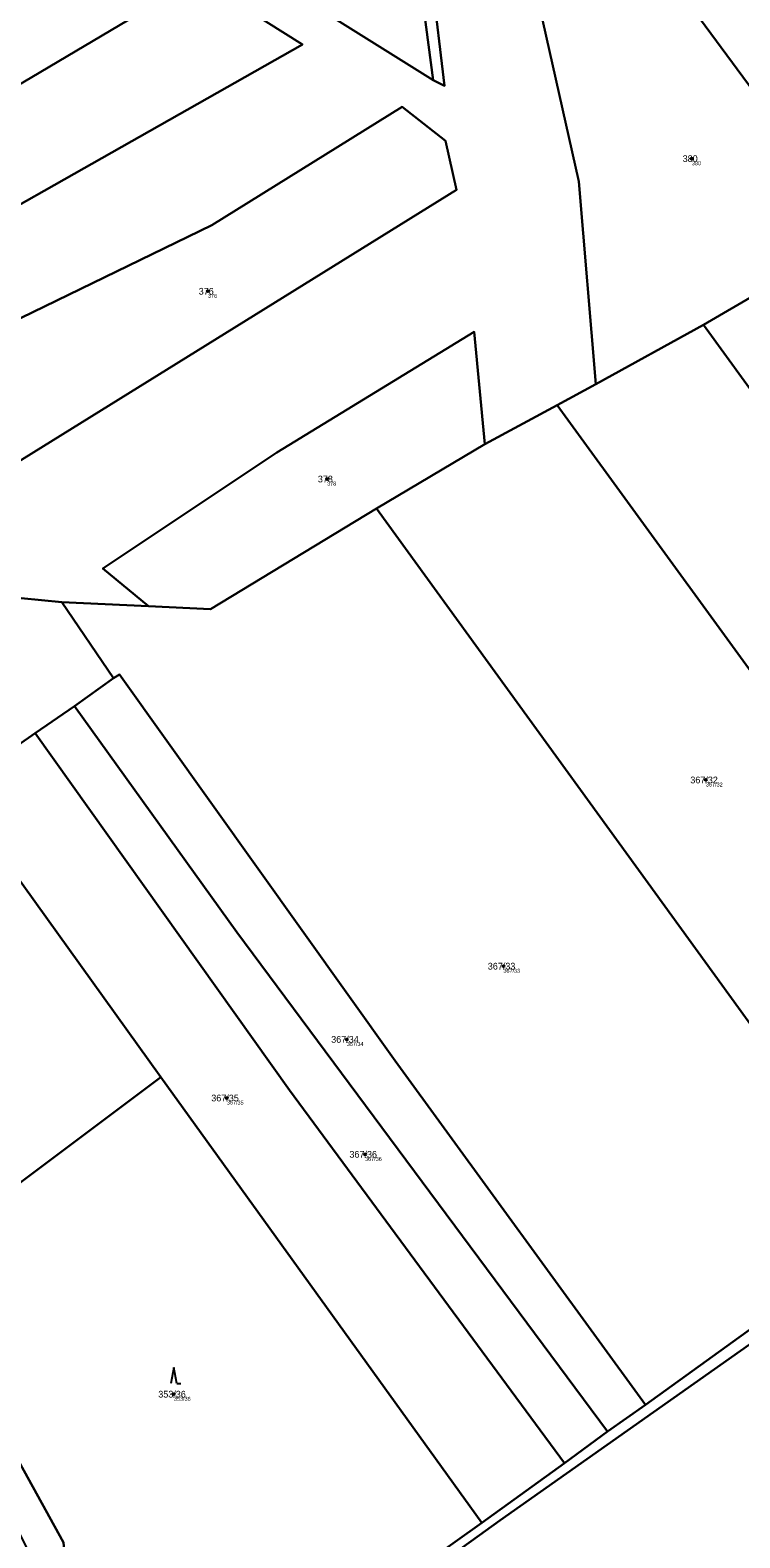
# Model space of a CAD drawing. Extents: x -700238 to -698499, y -1070626 to -1068006.
# Drawn here: x -699862.2 to -699683.1, y -1070432.3 to -1070051.8 of the extents above; entities that cross this region are included whole.
import ezdxf

# ---------------------------------------------------------------- set-up
doc = ezdxf.new("R2010")
doc.units = 0
for name, color, linetype in [('Definiční body', 7, 'Continuous'), ('Hranice parcel', 7, 'Continuous'), ('Parcelní čísla', 7, 'Continuous'), ('Polygon parcely', 7, 'Continuous'), ('Značky kultur', 7, 'Continuous')]:
    doc.layers.add(name, color=color, linetype=linetype)

msp = doc.modelspace()

# ---------------------------------------------------------------- linework, layer by layer
at = {"layer": 'Definiční body'}
for centre in [(-699695.22, -1070084.23994), (-699817.36, -1070117.69994), (-699787.29, -1070165.07994), (-699691.67, -1070241.01994), (-699742.78, -1070288.01994), (-699782.3, -1070306.48994), (-699812.57, -1070321.28994), (-699777.7, -1070335.49994), (-699825.94, -1070396.02994)]:
    msp.add_circle(centre, 0.25, dxfattribs=at)
at = {"layer": 'Hranice parcel'}
for p, q in [((-699760.48, -1070064.46), (-699764.05, -1070037.6)), ((-699692.3, -1070126.13), (-699719.44, -1070141.14)), ((-699719.44, -1070141.14), (-699729.26, -1070146.47)), ((-699729.26, -1070146.47), (-699747.49, -1070156.31)), ((-699747.49, -1070156.31), (-699774.82, -1070172.56)), ((-699841.16, -1070215.36), (-699854.27, -1070196.19)), ((-699832.38, -1070197.19), (-699854.27, -1070196.19)), ((-699851.06, -1070222.38), (-699841.16, -1070215.36)), ((-699860.99, -1070229.24), (-699851.06, -1070222.38)), ((-699881.39, -1070243.41), (-699860.99, -1070229.24)), ((-699881.39, -1070243.41), (-699829.22, -1070316.05)), ((-699829.22, -1070316.05), (-699882.86, -1070356.11)), ((-699748.23, -1070428.52), (-699829.22, -1070316.05)), ((-699643.87, -1070353.19), (-699706.96, -1070398.68)), ((-699706.96, -1070398.68), (-699716.55, -1070405.48)), ((-699716.55, -1070405.48), (-699727.35, -1070413.42)), ((-699727.35, -1070413.42), (-699748.23, -1070428.52)), ((-699823.69, -1070482.27), (-699748.23, -1070428.52))]:
    msp.add_line(p, q, dxfattribs=at)
for points in [[(-699773.88, -1069925.87), (-699775.47, -1069950.06), (-699776.09, -1069961.97), (-699774.25, -1069975.35), (-699760.75, -1070039.69), (-699757.63, -1070065.88), (-699760.48, -1070064.46)], [(-699760.48, -1070064.46), (-699814.07, -1070030.89), (-699916.79, -1069973.61), (-699963.55, -1069943.05)], [(-699854.27, -1070196.19), (-699869.64, -1070194.62), (-699892.83, -1070188.84), (-699913.08, -1070162.82), (-699928.47, -1070131.78), (-699793.52, -1070055.46), (-699819.94, -1070038.73), (-699903.8, -1070088.48), (-699881.47, -1070036.48), (-699859.27, -1070018.12), (-699893.51, -1069998.97), (-699909.95, -1070034.69), (-699926.64, -1070077.05), (-699936.46, -1070111.92), (-699945.42, -1070093.75), (-699957.78, -1070077.02), (-699945.33, -1070038.99), (-699924.07, -1069992.37), (-699973.03, -1069961.64)], [(-699719.44, -1070141.14), (-699723.72, -1070090.01), (-699733.66, -1070045.81), (-699736.31, -1069990.62)], [(-699736.31, -1069990.62), (-699727.1, -1070003.14), (-699698.54, -1070041.6), (-699662.16, -1070090.9)], [(-699882.78, -1070133.22), (-699816.4, -1070100.98), (-699768.36, -1070071.18), (-699757.42, -1070079.73), (-699754.62, -1070092.08), (-699868.61, -1070162.84), (-699882.78, -1070133.22)], [(-699667.65, -1070125.9), (-699678.56, -1070118.21), (-699692.3, -1070126.13)], [(-699832.38, -1070197.19), (-699843.91, -1070187.63), (-699799.97, -1070158.41), (-699750.15, -1070127.96), (-699747.49, -1070156.31)], [(-699692.3, -1070126.13), (-699631.14, -1070210.34), (-699566.95, -1070298.71)], [(-699729.26, -1070146.47), (-699663.22, -1070237.21), (-699601.03, -1070322.49)], [(-699774.82, -1070172.56), (-699816.69, -1070197.91), (-699832.38, -1070197.19)], [(-699774.82, -1070172.56), (-699708.7, -1070263.67), (-699643.87, -1070353.19)], [(-699841.16, -1070215.36), (-699839.71, -1070214.44), (-699770.11, -1070311.9), (-699706.96, -1070398.68)], [(-699851.06, -1070222.38), (-699810.03, -1070279.46), (-699716.55, -1070405.48)], [(-699727.35, -1070413.42), (-699796.81, -1070319.27), (-699860.99, -1070229.24)], [(-699882.86, -1070356.11), (-699869.32, -1070405.39), (-699853.83, -1070433.45), (-699852.48, -1070448.98)], [(-699822, -1070484.36), (-699743.66, -1070427.93), (-699677.85, -1070381.45)]]:
    msp.add_lwpolyline(points, dxfattribs=at)
at = {"layer": 'Polygon parcely'}
for points in [[(-699764.05, -1070037.6), (-699857.82, -1069980.05), (-699953.34, -1069921.42), (-699963.55, -1069943.05), (-699916.79, -1069973.61), (-699814.07, -1070030.89), (-699760.48, -1070064.46)], [(-699776.82, -1069919.37), (-699778.54, -1069940.11), (-699779.64, -1069961.35), (-699777.09, -1069979.45), (-699771.94, -1070003.65), (-699764.05, -1070037.6), (-699760.48, -1070064.46), (-699757.63, -1070065.88), (-699760.75, -1070039.69), (-699774.25, -1069975.35), (-699776.09, -1069961.97), (-699775.47, -1069950.06), (-699773.88, -1069925.87)], [(-699660.76, -1070101.89), (-699662.16, -1070090.9), (-699698.54, -1070041.6), (-699727.1, -1070003.14), (-699736.31, -1069990.62), (-699733.66, -1070045.81), (-699723.72, -1070090.01), (-699719.44, -1070141.14), (-699692.3, -1070126.13), (-699678.56, -1070118.21), (-699667.65, -1070125.9)], [(-699882.78, -1070133.22), (-699816.4, -1070100.98), (-699768.36, -1070071.18), (-699757.42, -1070079.73), (-699754.62, -1070092.08), (-699868.61, -1070162.84)], [(-699882.78, -1070133.22), (-699868.61, -1070162.84), (-699754.62, -1070092.08), (-699757.42, -1070079.73), (-699768.36, -1070071.18), (-699816.4, -1070100.98)], [(-699692.3, -1070126.13), (-699631.14, -1070210.34), (-699566.95, -1070298.71), (-699532.26, -1070273.57), (-699557.41, -1070250.21), (-699564.16, -1070237.68), (-699598.77, -1070199.01), (-699620.85, -1070177.77), (-699654.36, -1070136.27), (-699664.49, -1070128.15), (-699667.65, -1070125.9), (-699678.56, -1070118.21)], [(-699747.49, -1070156.31), (-699750.15, -1070127.96), (-699799.97, -1070158.41), (-699843.91, -1070187.63), (-699832.38, -1070197.19), (-699816.69, -1070197.91), (-699774.82, -1070172.56)], [(-699719.44, -1070141.14), (-699729.26, -1070146.47), (-699663.22, -1070237.21), (-699601.03, -1070322.49), (-699566.95, -1070298.71), (-699631.14, -1070210.34), (-699692.3, -1070126.13)], [(-699747.49, -1070156.31), (-699774.82, -1070172.56), (-699708.7, -1070263.67), (-699643.87, -1070353.19), (-699601.03, -1070322.49), (-699663.22, -1070237.21), (-699729.26, -1070146.47)], [(-699854.27, -1070196.19), (-699841.16, -1070215.36), (-699839.71, -1070214.44), (-699770.11, -1070311.9), (-699706.96, -1070398.68), (-699643.87, -1070353.19), (-699708.7, -1070263.67), (-699774.82, -1070172.56), (-699816.69, -1070197.91), (-699832.38, -1070197.19)], [(-699810.03, -1070279.46), (-699716.55, -1070405.48), (-699706.96, -1070398.68), (-699770.11, -1070311.9), (-699839.71, -1070214.44), (-699841.16, -1070215.36), (-699851.06, -1070222.38)], [(-699716.55, -1070405.48), (-699810.03, -1070279.46), (-699851.06, -1070222.38), (-699860.99, -1070229.24), (-699796.81, -1070319.27), (-699727.35, -1070413.42)], [(-699829.22, -1070316.05), (-699748.23, -1070428.52), (-699727.35, -1070413.42), (-699796.81, -1070319.27), (-699860.99, -1070229.24), (-699881.39, -1070243.41)], [(-699908.34, -1070303.23), (-699902.91, -1070313.7), (-699897.86, -1070317.82), (-699885.7, -1070336.85), (-699882.86, -1070356.11), (-699829.22, -1070316.05), (-699881.39, -1070243.41), (-699907.2, -1070262.01), (-699925.21, -1070275.42), (-699911.78, -1070295.95)], [(-699716.55, -1070405.48), (-699727.35, -1070413.42), (-699748.23, -1070428.52), (-699823.69, -1070482.27), (-699822, -1070484.36), (-699743.66, -1070427.93), (-699677.85, -1070381.45), (-699674.72, -1070379.2), (-699599.15, -1070324.86), (-699530.63, -1070276.48), (-699519.38, -1070263.27), (-699522, -1070259.73), (-699532.26, -1070273.57), (-699566.95, -1070298.71), (-699601.03, -1070322.49), (-699643.87, -1070353.19), (-699706.96, -1070398.68)], [(-699852.48, -1070448.98), (-699823.69, -1070482.27), (-699748.23, -1070428.52), (-699829.22, -1070316.05), (-699882.86, -1070356.11), (-699869.32, -1070405.39), (-699853.83, -1070433.45)], [(-699873.23, -1070414.3), (-699863.46, -1070434.09), (-699860.81, -1070439.46), (-699865.99, -1070452.05), (-699852.48, -1070448.98), (-699853.83, -1070433.45), (-699869.32, -1070405.39), (-699882.86, -1070356.11), (-699888.79, -1070358.09), (-699892.49, -1070364.5), (-699893.45, -1070371.29), (-699889.73, -1070381.16), (-699891.17, -1070389.56), (-699888.47, -1070392.83), (-699875.28, -1070403.97), (-699873.4, -1070407.52)], [(-699780.72, -1070531.14), (-699641.57, -1070432.96), (-699677.85, -1070381.45), (-699743.66, -1070427.93), (-699822, -1070484.36), (-699797.94, -1070511.03), (-699785.02, -1070524.73)]]:
    msp.add_lwpolyline(points, close=True, dxfattribs=at)
for points in [[(-699760.75, -1070039.69), (-699757.63, -1070065.88), (-699760.48, -1070064.46), (-699814.07, -1070030.89)], [(-700010.65, -1070036.99), (-700025.83, -1070074.31), (-700025.92, -1070097.31), (-700022.52, -1070128.11), (-699999.64, -1070139.83), (-699975.46, -1070149.9), (-699947.73, -1070160.45), (-699945.28, -1070166.1), (-699971.91, -1070154.81), (-699970.29, -1070157.57), (-699907.2, -1070262.01), (-699881.39, -1070243.41), (-699860.99, -1070229.24), (-699851.06, -1070222.38), (-699841.16, -1070215.36), (-699854.27, -1070196.19), (-699869.64, -1070194.62), (-699892.83, -1070188.84), (-699913.08, -1070162.82), (-699928.47, -1070131.78), (-699793.52, -1070055.46), (-699819.94, -1070038.73), (-699903.8, -1070088.48), (-699881.47, -1070036.48)], [(-699881.47, -1070036.48), (-699903.8, -1070088.48), (-699819.94, -1070038.73), (-699793.52, -1070055.46), (-699928.47, -1070131.78), (-699913.08, -1070162.82), (-699892.83, -1070188.84), (-699869.64, -1070194.62), (-699854.27, -1070196.19), (-699832.38, -1070197.19), (-699843.91, -1070187.63), (-699799.97, -1070158.41), (-699750.15, -1070127.96), (-699747.49, -1070156.31), (-699729.26, -1070146.47), (-699719.44, -1070141.14), (-699723.72, -1070090.01), (-699733.66, -1070045.81)], [(-699698.54, -1070041.6), (-699662.16, -1070090.9), (-699656.19, -1070099.08), (-699628.72, -1070136.07), (-699573.37, -1070201.88), (-699522, -1070259.73), (-699519.38, -1070263.27), (-699508.46, -1070275.17), (-699486.72, -1070296.69), (-699474.56, -1070305.15), (-699457.77, -1070313.62), (-699430.94, -1070324.73), (-699410.85, -1070331.73), (-699396.04, -1070338.88), (-699374.89, -1070351.04), (-699341.58, -1070369.26), (-699311.56, -1070386.55)]]:
    msp.add_lwpolyline(points, dxfattribs=at)
at = {"layer": 'Značky kultur'}
for p, q in [((-699825.94, -1070389.33), (-699826.69, -1070393.33)), ((-699825.19, -1070393.33), (-699825.94, -1070389.33)), ((-699825.19, -1070393.33), (-699824.194, -1070393.33))]:
    msp.add_line(p, q, dxfattribs=at)

# ---------------------------------------------------------------- texts
at = {"layer": 'Definiční body'}
for s, p in [('380', (-699695.22, -1070085.896)), ('376', (-699817.36, -1070119.356)), ('378', (-699787.29, -1070166.736)), ('367/32', (-699691.67, -1070242.676)), ('367/33', (-699742.78, -1070289.676)), ('367/34', (-699782.3, -1070308.146)), ('367/35', (-699812.57, -1070322.946)), ('367/36', (-699777.7, -1070337.156)), ('353/36', (-699825.94, -1070397.686))]:
    msp.add_text(s, height=0.999996, dxfattribs=at).set_placement(p)
at = {"layer": 'Parcelní čísla'}
for s, p in [('380', (-699697.545, -1070085.09)), ('376', (-699819.685, -1070118.55)), ('378', (-699789.615, -1070165.93)), ('367/32', (-699695.617, -1070241.87)), ('367/33', (-699746.727, -1070288.87)), ('367/34', (-699786.247, -1070307.34)), ('367/35', (-699816.517, -1070322.14)), ('367/36', (-699781.647, -1070336.35)), ('353/36', (-699829.887, -1070396.88))]:
    msp.add_text(s, height=1.699998, dxfattribs=at).set_placement(p)

doc.saveas('drawing.dxf')
